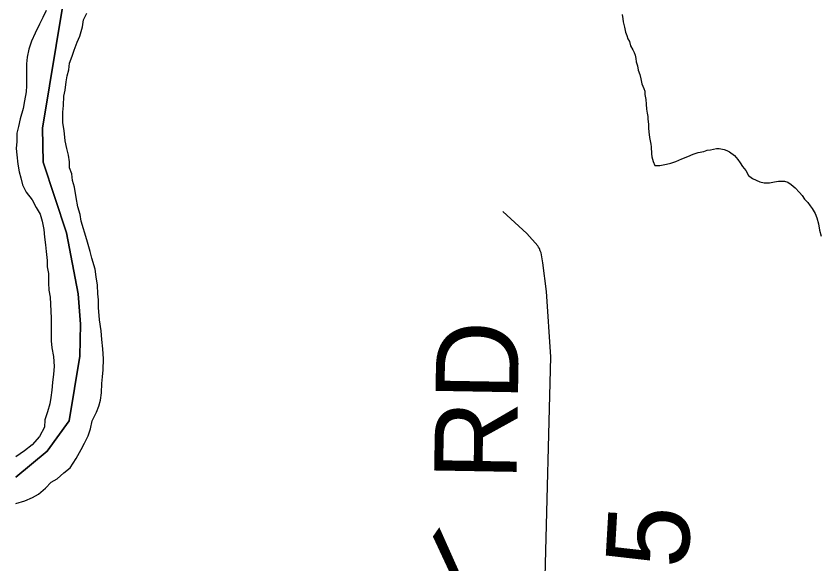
# Model space of a CAD drawing. Extents: x -59 to 82, y -3 to 49.
# Drawn here: x -51.748 to -51.194, y 44.317 to 44.695 of the extents above; entities that cross this region are included whole.
import ezdxf

# ---------------------------------------------------------------- set-up
doc = ezdxf.new("R2010")
doc.units = 0
for name, color, linetype in [('GM_X_Corporation', 7, 'Continuous'), ('GM_X_Major_River', 7, 'Continuous'), ('GM_X_Minor_River', 7, 'Continuous'), ('GM_X_Township_Road', 7, 'Continuous'), ('GM_X_Township_Road_Text', 7, 'Continuous')]:
    doc.layers.add(name, color=color, linetype=linetype)

msp = doc.modelspace()

# ---------------------------------------------------------------- linework, layer by layer
at = {"layer": 'GM_X_Corporation'}
for p, q in [((-51.73031, 44.6173), (-51.71606, 44.70341)), ((-51.71606, 44.70341), (-51.73031, 44.6173)), ((-51.72985, 44.59376), (-51.73031, 44.6173)), ((-51.73031, 44.6173), (-51.72985, 44.59376)), ((-51.71371, 44.54507), (-51.72985, 44.59376)), ((-51.72985, 44.59376), (-51.71371, 44.54507)), ((-51.70568, 44.50307), (-51.71371, 44.54507)), ((-51.71371, 44.54507), (-51.70568, 44.50307)), ((-51.70414, 44.4822), (-51.70568, 44.50307)), ((-51.70568, 44.50307), (-51.70414, 44.4822)), ((-51.70446, 44.46017), (-51.70414, 44.4822)), ((-51.70414, 44.4822), (-51.70446, 44.46017)), ((-51.71193, 44.41559), (-51.70446, 44.46017)), ((-51.70446, 44.46017), (-51.71193, 44.41559)), ((-51.72708, 44.39478), (-51.71193, 44.41559)), ((-51.71193, 44.41559), (-51.72708, 44.39478)), ((-51.74874, 44.37689), (-51.72708, 44.39478)), ((-51.72708, 44.39478), (-51.74874, 44.37689))]:
    msp.add_line(p, q, dxfattribs=at)
at = {"layer": 'GM_X_Major_River'}
for p, q in [((-51.72772, 44.69841), (-51.72998, 44.69348)), ((-51.72998, 44.69348), (-51.73224, 44.68893)), ((-51.70271, 44.68707), (-51.70197, 44.692)), ((-51.70197, 44.692), (-51.6997, 44.69656)), ((-51.73224, 44.68893), (-51.73526, 44.68285)), ((-51.70459, 44.68062), (-51.70271, 44.68707)), ((-51.73526, 44.68285), (-51.7379, 44.67716)), ((-51.70647, 44.67645), (-51.70459, 44.68062)), ((-51.7379, 44.67716), (-51.73978, 44.67185)), ((-51.70836, 44.67113), (-51.70647, 44.67645)), ((-51.73978, 44.67185), (-51.7409, 44.66616)), ((-51.70986, 44.66696), (-51.70836, 44.67113)), ((-51.7409, 44.66616), (-51.74127, 44.6616)), ((-51.71174, 44.66203), (-51.70986, 44.66696)), ((-51.74127, 44.6616), (-51.74124, 44.64644)), ((-51.71211, 44.65748), (-51.71174, 44.66203)), ((-51.71399, 44.64913), (-51.71324, 44.6533)), ((-51.71324, 44.6533), (-51.71211, 44.65748)), ((-51.71473, 44.64344), (-51.71399, 44.64913)), ((-51.74161, 44.64226), (-51.74273, 44.63619)), ((-51.74124, 44.64644), (-51.74161, 44.64226)), ((-51.71548, 44.63927), (-51.71473, 44.64344)), ((-51.74273, 44.63619), (-51.74348, 44.63088)), ((-51.71585, 44.63282), (-51.71548, 44.63927)), ((-51.74348, 44.63088), (-51.74573, 44.62367)), ((-51.71622, 44.62827), (-51.71585, 44.63282)), ((-51.7162, 44.62106), (-51.71622, 44.62827)), ((-51.74573, 44.62367), (-51.74686, 44.61836)), ((-51.71543, 44.61575), (-51.7162, 44.62106)), ((-51.74686, 44.61836), (-51.74798, 44.61381)), ((-51.74798, 44.61381), (-51.74797, 44.60812)), ((-51.71466, 44.60855), (-51.71543, 44.61575)), ((-51.74797, 44.60812), (-51.74834, 44.60319)), ((-51.71351, 44.60324), (-51.71466, 44.60855)), ((-51.74834, 44.60319), (-51.74795, 44.59902)), ((-51.71237, 44.59869), (-51.71351, 44.60324)), ((-51.74795, 44.59902), (-51.74718, 44.59257)), ((-51.7116, 44.59414), (-51.71237, 44.59869)), ((-51.74718, 44.59257), (-51.74641, 44.58726)), ((-51.71159, 44.58997), (-51.7116, 44.59414)), ((-51.74641, 44.58726), (-51.74527, 44.58309)), ((-51.71007, 44.5858), (-51.71159, 44.58997)), ((-51.70968, 44.58125), (-51.71007, 44.5858)), ((-51.74527, 44.58309), (-51.74412, 44.57816)), ((-51.70816, 44.5767), (-51.70968, 44.58125)), ((-51.74412, 44.57816), (-51.74146, 44.57323)), ((-51.70701, 44.56949), (-51.70816, 44.5767)), ((-51.74146, 44.57323), (-51.73729, 44.56793)), ((-51.70586, 44.56305), (-51.70701, 44.56949)), ((-51.73729, 44.56793), (-51.73463, 44.56263)), ((-51.73463, 44.56263), (-51.73197, 44.55808)), ((-51.73197, 44.55808), (-51.73044, 44.55315)), ((-51.70433, 44.55774), (-51.70586, 44.56305)), ((-51.73044, 44.55315), (-51.72929, 44.54746)), ((-51.70356, 44.55319), (-51.70433, 44.55774)), ((-51.69975, 44.5403), (-51.70356, 44.55319)), ((-51.72929, 44.54746), (-51.7289, 44.54215)), ((-51.7289, 44.54215), (-51.72814, 44.53684)), ((-51.72814, 44.53684), (-51.72775, 44.53229)), ((-51.69746, 44.53234), (-51.69975, 44.5403)), ((-51.72775, 44.53229), (-51.72698, 44.52622)), ((-51.69632, 44.52779), (-51.69746, 44.53234)), ((-51.72698, 44.52622), (-51.72697, 44.52167)), ((-51.69403, 44.5202), (-51.69632, 44.52779)), ((-51.72697, 44.52167), (-51.7262, 44.51712)), ((-51.69326, 44.51489), (-51.69403, 44.5202)), ((-51.7262, 44.51712), (-51.72619, 44.51067)), ((-51.69249, 44.50921), (-51.69326, 44.51489)), ((-51.72619, 44.51067), (-51.7258, 44.50574)), ((-51.6921, 44.50314), (-51.69249, 44.50921)), ((-51.7258, 44.50574), (-51.72503, 44.50081)), ((-51.69171, 44.49897), (-51.6921, 44.50314)), ((-51.72503, 44.50081), (-51.72424, 44.4864)), ((-51.6917, 44.49366), (-51.69171, 44.49897)), ((-51.69093, 44.48531), (-51.6917, 44.49366)), ((-51.72424, 44.4864), (-51.72421, 44.47085)), ((-51.68978, 44.47773), (-51.69093, 44.48531)), ((-51.68938, 44.47166), (-51.68978, 44.47773)), ((-51.72421, 44.47085), (-51.72382, 44.46592)), ((-51.68861, 44.46521), (-51.68938, 44.47166)), ((-51.72382, 44.46592), (-51.72267, 44.45985)), ((-51.68822, 44.45839), (-51.68861, 44.46521)), ((-51.72267, 44.45985), (-51.72228, 44.45302)), ((-51.68858, 44.4508), (-51.68822, 44.45839)), ((-51.72228, 44.45302), (-51.72265, 44.44771)), ((-51.72265, 44.44771), (-51.72339, 44.44202)), ((-51.68895, 44.44587), (-51.68858, 44.4508)), ((-51.72339, 44.44202), (-51.72376, 44.43671)), ((-51.68932, 44.44132), (-51.68895, 44.44587)), ((-51.72376, 44.43671), (-51.72451, 44.43178)), ((-51.68968, 44.43487), (-51.68932, 44.44132)), ((-51.72451, 44.43178), (-51.72525, 44.42723)), ((-51.69043, 44.42994), (-51.68968, 44.43487)), ((-51.72525, 44.42723), (-51.72676, 44.42192)), ((-51.69306, 44.42159), (-51.69156, 44.42576)), ((-51.69156, 44.42576), (-51.69043, 44.42994)), ((-51.72676, 44.42192), (-51.72864, 44.41622)), ((-51.69608, 44.41551), (-51.69306, 44.42159)), ((-51.72864, 44.41622), (-51.72901, 44.41129)), ((-51.6972, 44.4102), (-51.69608, 44.41551)), ((-51.72901, 44.41129), (-51.7324, 44.40484)), ((-51.69871, 44.40527), (-51.6972, 44.4102)), ((-51.7324, 44.40484), (-51.73731, 44.39914)), ((-51.70135, 44.40033), (-51.69871, 44.40527)), ((-51.73731, 44.39914), (-51.7426, 44.39496)), ((-51.70361, 44.39578), (-51.70135, 44.40033)), ((-51.7426, 44.39496), (-51.74865, 44.39078)), ((-51.707, 44.3897), (-51.70361, 44.39578)), ((-51.71115, 44.38325), (-51.707, 44.3897)), ((-51.71569, 44.37983), (-51.71115, 44.38325)), ((-51.72438, 44.37337), (-51.72022, 44.37565)), ((-51.72022, 44.37565), (-51.71569, 44.37983)), ((-51.72816, 44.36919), (-51.72438, 44.37337)), ((-51.73723, 44.36273), (-51.73307, 44.36501)), ((-51.73307, 44.36501), (-51.72816, 44.36919)), ((-51.74858, 44.35854), (-51.74253, 44.36044)), ((-51.74253, 44.36044), (-51.73723, 44.36273))]:
    msp.add_line(p, q, dxfattribs=at)
at = {"layer": 'GM_X_Minor_River'}
for p, q in [((-51.33108, 44.69559), (-51.33068, 44.69255)), ((-51.33068, 44.69255), (-51.33028, 44.69065)), ((-51.33028, 44.69065), (-51.32989, 44.68875)), ((-51.32989, 44.68875), (-51.32949, 44.68685)), ((-51.32949, 44.68685), (-51.32871, 44.68344)), ((-51.32871, 44.68344), (-51.32793, 44.68116)), ((-51.32793, 44.68116), (-51.32715, 44.67889)), ((-51.32715, 44.67889), (-51.326, 44.67699)), ((-51.326, 44.67699), (-51.32521, 44.67395)), ((-51.32521, 44.67395), (-51.32367, 44.67131)), ((-51.32367, 44.67131), (-51.3229, 44.66941)), ((-51.3229, 44.66941), (-51.32212, 44.66752)), ((-51.32212, 44.66752), (-51.32172, 44.66524)), ((-51.32172, 44.66524), (-51.32132, 44.66296)), ((-51.32132, 44.66296), (-51.32054, 44.6603)), ((-51.32054, 44.6603), (-51.32014, 44.65726)), ((-51.32014, 44.65726), (-51.31897, 44.65423)), ((-51.31897, 44.65423), (-51.31819, 44.65119)), ((-51.31819, 44.65119), (-51.3174, 44.64778)), ((-51.3174, 44.64778), (-51.31624, 44.64474)), ((-51.31624, 44.64474), (-51.31547, 44.64285)), ((-51.31547, 44.64285), (-51.31545, 44.64057)), ((-51.31545, 44.64057), (-51.31466, 44.63715)), ((-51.31466, 44.63715), (-51.31463, 44.63373)), ((-51.31463, 44.63373), (-51.31422, 44.63031)), ((-51.31422, 44.63031), (-51.31382, 44.62765)), ((-51.31382, 44.62765), (-51.31343, 44.62537)), ((-51.31343, 44.62537), (-51.31341, 44.62347)), ((-51.31341, 44.62347), (-51.313, 44.62005)), ((-51.313, 44.62005), (-51.31298, 44.61739)), ((-51.31298, 44.61739), (-51.31258, 44.61473)), ((-51.31258, 44.61473), (-51.31217, 44.61093)), ((-51.31217, 44.61093), (-51.31177, 44.60866)), ((-51.31177, 44.60866), (-51.31137, 44.60638)), ((-51.31137, 44.60638), (-51.31098, 44.60448)), ((-51.31098, 44.60448), (-51.31094, 44.59953)), ((-51.27261, 44.60208), (-51.27033, 44.60248)), ((-51.27033, 44.60248), (-51.26805, 44.60287)), ((-51.26805, 44.60287), (-51.26616, 44.60327)), ((-51.26616, 44.60327), (-51.26426, 44.60328)), ((-51.26426, 44.60328), (-51.26084, 44.60254)), ((-51.26084, 44.60254), (-51.25893, 44.6018)), ((-51.31094, 44.59953), (-51.31054, 44.59764)), ((-51.31054, 44.59764), (-51.30976, 44.59422)), ((-51.29003, 44.59626), (-51.28586, 44.59781)), ((-51.28586, 44.59781), (-51.28208, 44.59935)), ((-51.28208, 44.59935), (-51.27867, 44.60052)), ((-51.27867, 44.60052), (-51.27488, 44.60131)), ((-51.27488, 44.60131), (-51.27261, 44.60208)), ((-51.25893, 44.6018), (-51.25703, 44.60105)), ((-51.25703, 44.60105), (-51.25359, 44.59841)), ((-51.25359, 44.59841), (-51.25129, 44.59577)), ((-51.30976, 44.59422), (-51.30859, 44.59157)), ((-51.30859, 44.59157), (-51.30518, 44.59159)), ((-51.30518, 44.59159), (-51.3029, 44.59199)), ((-51.3029, 44.59199), (-51.30063, 44.59238)), ((-51.30063, 44.59238), (-51.29759, 44.59317)), ((-51.29759, 44.59317), (-51.29419, 44.59433)), ((-51.29419, 44.59433), (-51.29003, 44.59626)), ((-51.25129, 44.59577), (-51.24975, 44.59349)), ((-51.24975, 44.59349), (-51.24821, 44.59084)), ((-51.24821, 44.59084), (-51.24591, 44.5882)), ((-51.24591, 44.5882), (-51.24398, 44.58479)), ((-51.24398, 44.58479), (-51.24131, 44.58253)), ((-51.24131, 44.58253), (-51.23635, 44.58028)), ((-51.23635, 44.58028), (-51.23331, 44.57954)), ((-51.22951, 44.57957), (-51.2261, 44.58035)), ((-51.2261, 44.58035), (-51.22345, 44.58075)), ((-51.22345, 44.58075), (-51.21927, 44.58078)), ((-51.21927, 44.58078), (-51.21699, 44.58003)), ((-51.23331, 44.57954), (-51.23141, 44.57955)), ((-51.23141, 44.57955), (-51.22951, 44.57957)), ((-51.21699, 44.58003), (-51.21469, 44.57853)), ((-51.21469, 44.57853), (-51.21202, 44.57627)), ((-51.21202, 44.57627), (-51.20895, 44.57286)), ((-51.20895, 44.57286), (-51.20704, 44.57098)), ((-51.20704, 44.57098), (-51.2055, 44.56833)), ((-51.2055, 44.56833), (-51.2032, 44.56606)), ((-51.2032, 44.56606), (-51.20167, 44.56379)), ((-51.20167, 44.56379), (-51.20013, 44.5619)), ((-51.20013, 44.5619), (-51.19821, 44.55849)), ((-51.19821, 44.55849), (-51.19704, 44.55546)), ((-51.19704, 44.55546), (-51.19587, 44.55128)), ((-51.19587, 44.55128), (-51.19508, 44.54711)), ((-51.19508, 44.54711), (-51.1939, 44.54293))]:
    msp.add_line(p, q, dxfattribs=at)
at = {"layer": 'GM_X_Township_Road'}
for p, q in [((-51.39676, 44.54462), (-51.41334, 44.55994)), ((-51.38923, 44.53621), (-51.39676, 44.54462)), ((-51.3886, 44.5352), (-51.38923, 44.53621)), ((-51.38798, 44.53443), (-51.3886, 44.5352)), ((-51.38743, 44.53285), (-51.38798, 44.53443)), ((-51.38688, 44.53137), (-51.38743, 44.53285)), ((-51.38563, 44.52457), (-51.38688, 44.53137)), ((-51.38322, 44.50485), (-51.38563, 44.52457)), ((-51.38024, 44.45969), (-51.38322, 44.50485)), ((-51.38406, 44.30818), (-51.38024, 44.45969))]:
    msp.add_line(p, q, dxfattribs=at)

# ---------------------------------------------------------------- texts
at = {"layer": 'GM_X_Township_Road_Text'}
for s, height, rotation, p in [('RD', 0.056818, 89.0091, (-51.40384, 44.3742)), ('5', 0.05682, 86.718, (-51.28597, 44.3133)), ('Y', 0.05682, 55.2995, (-51.43818, 44.26965))]:
    msp.add_text(s, height=height, rotation=rotation, dxfattribs=at).set_placement(p)

doc.saveas('drawing.dxf')
